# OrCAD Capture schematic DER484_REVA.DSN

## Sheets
1 PAGE3: size C
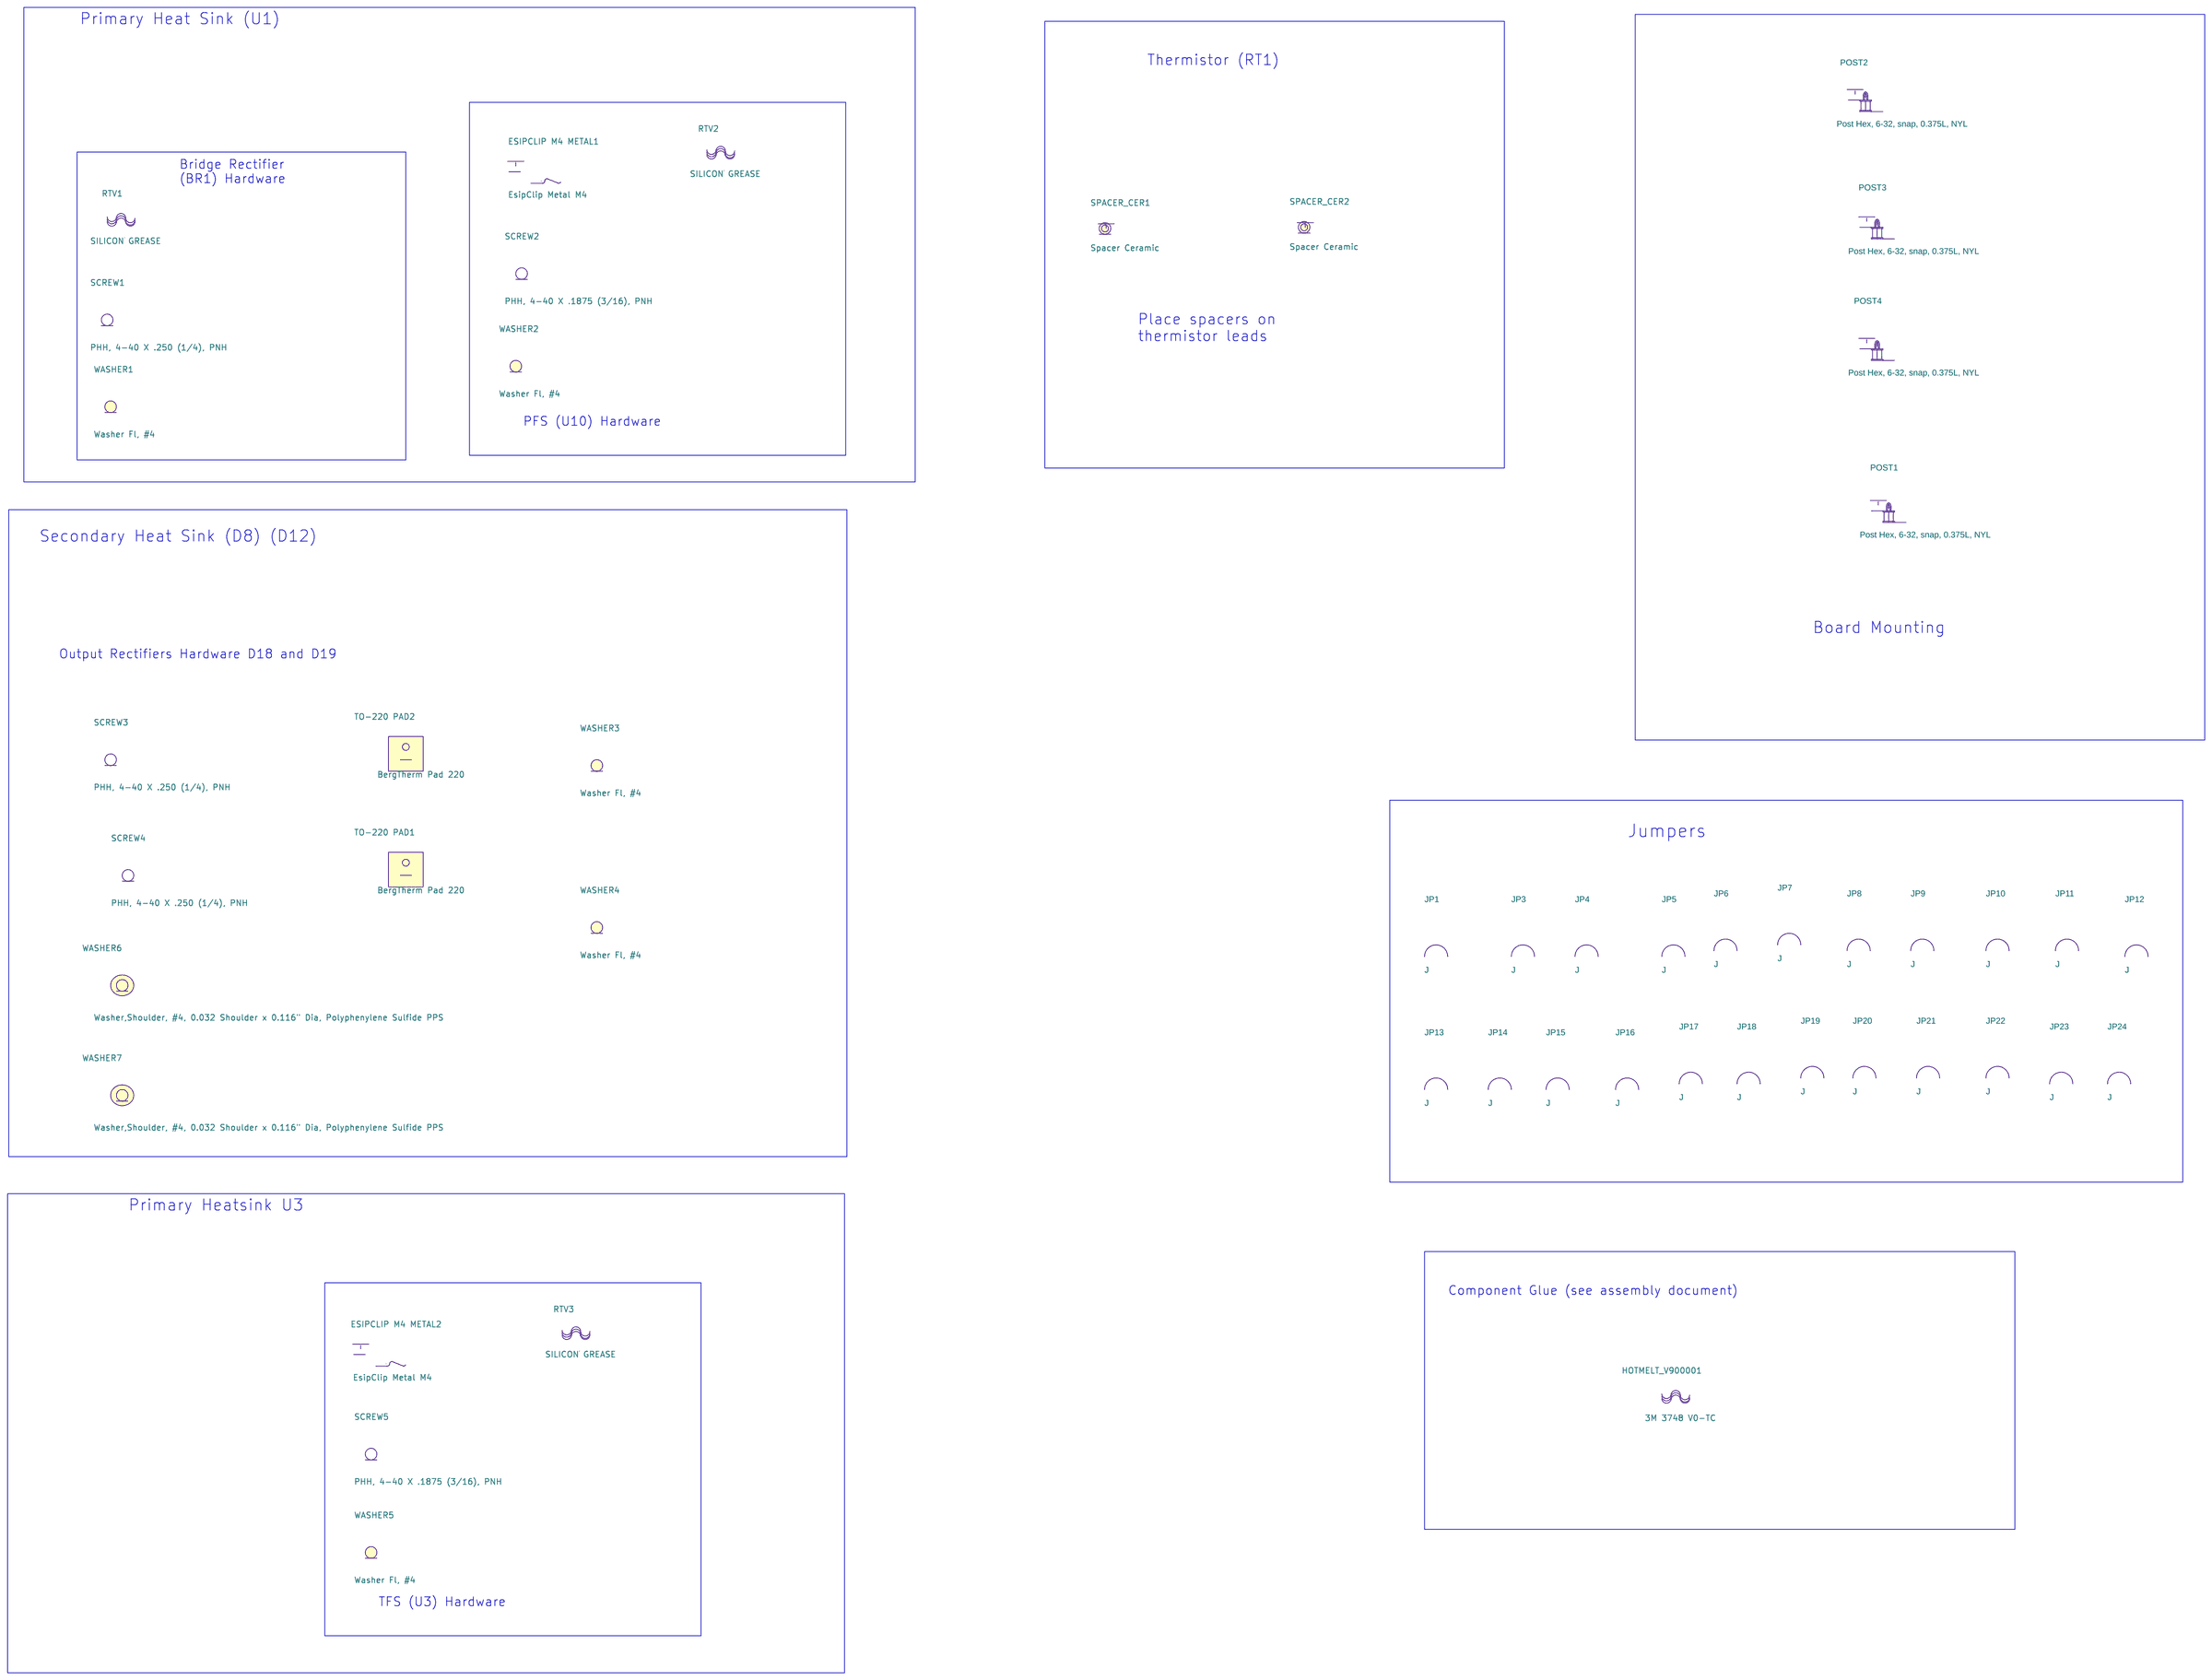
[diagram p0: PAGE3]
2 PAGE2: size C
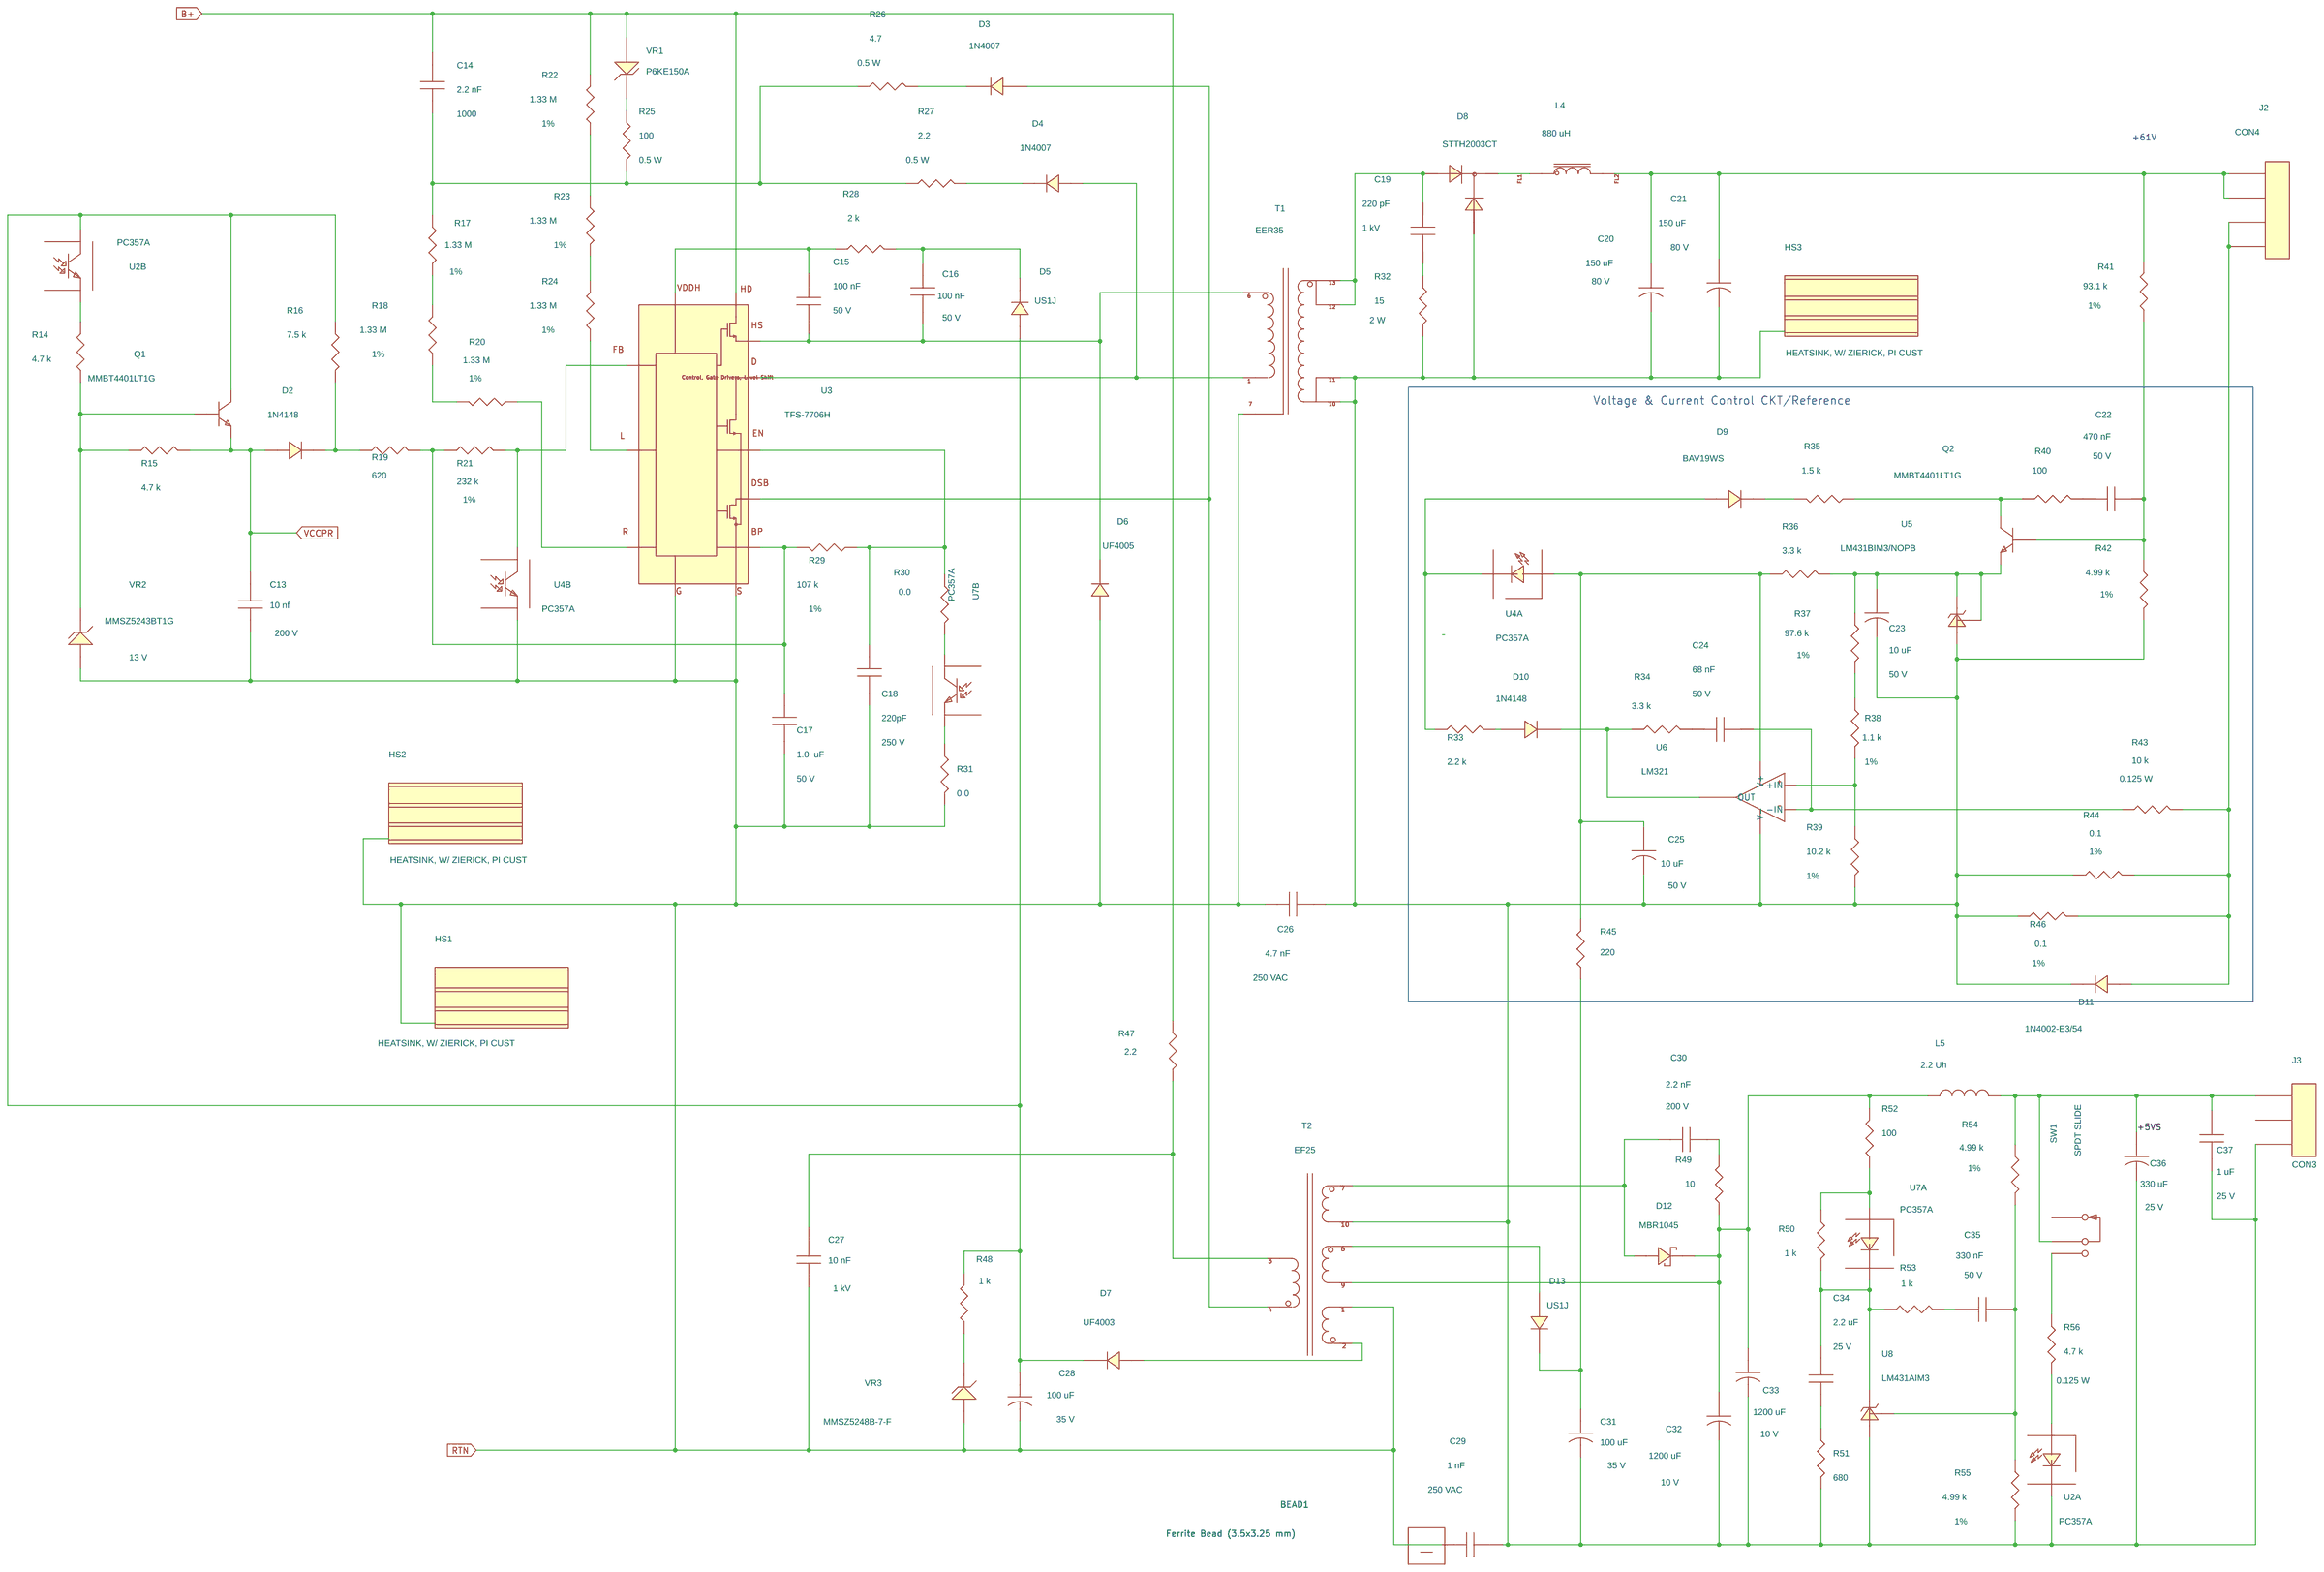
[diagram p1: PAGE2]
3 PAGE1: size C; title: DER-309; rev: A
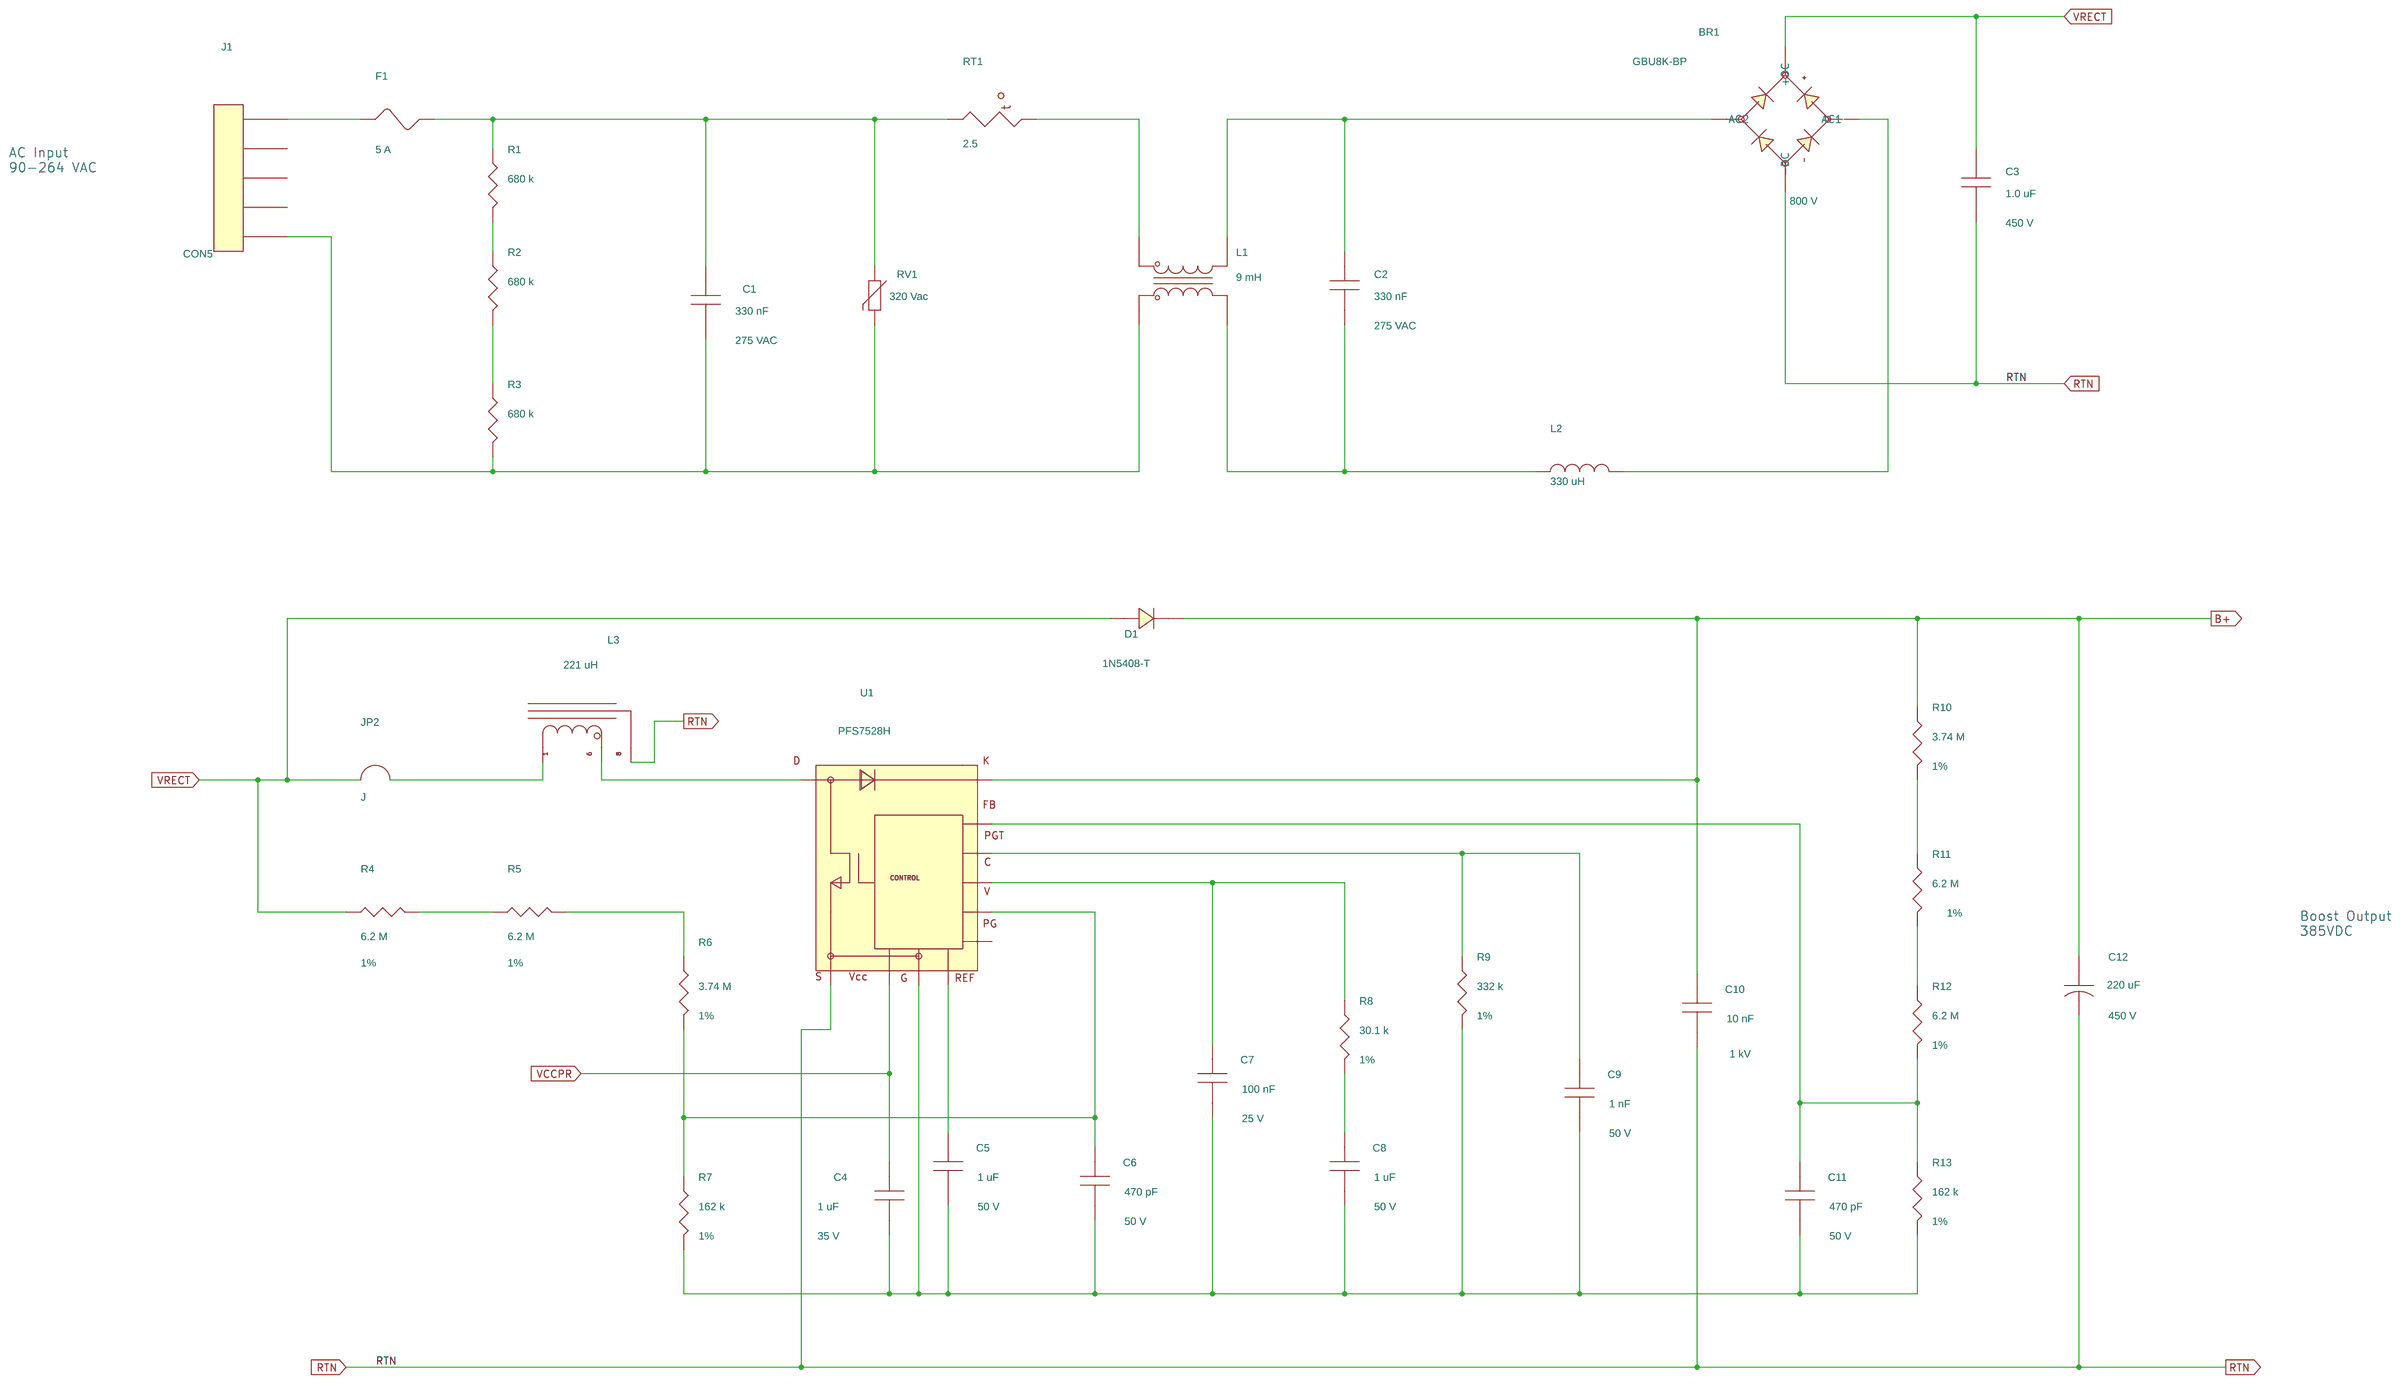
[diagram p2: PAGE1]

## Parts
sheet PAGE1
BR1  GBU8K-BP  [pidaxbridgegbu8]
C1  330 nF  [pinpcaprad760x380590050]
C2  330 nF  [pinpcaprad760x380590050]
C3  1.0 uF  [pi_np_cap_rad715x370ls590d050]
C4  1 uF  [pismc0603]
C5  1 uF  [pismc0805]
C6  470 pF  [pismc0805]
C7  100 nF  [pismc0805]
C8  1 uF  [pismc0805]
C9  1 nF  [pismc0805]
C10  10 nF  [pinpcaprad500x180250040]
C11  470 pF  [pismc0805]
C12  220 uF  [pi_polcap_cly_1181ls400d081]
D1  1N5408-T  [pidv300x200x060do15d0201ad]
F1  5 A  [pi_tr5_submin_fuse]
J1  CON5  [pi_hdr_5pin]
JP2  J  [pi_jumper200]
L1  9 mH  [pi_ind_4p_500x1050ls450d46_r1]
L2  330 uH  [pi_toroid_2p_550x950_ls480_d050]
L3  221 uH  [pi_bobbin_bpq32_20_DER484]
R1  680 k  [pismr1206]
R2  680 k  [pismr1206]
R3  680 k  [pismr1206]
R4  6.2 M  [pismr1206]
R5  6.2 M  [pismr1206]
R6  3.74 M  [pi14wvresd100ls100d030]
R7  162 k  [pismr0805]
R8  30.1 k  [pismr0805]
R9  332 k  [pismr0805]
R10  3.74 M  [pi14wvresd100ls100d030]
R11  6.2 M  [pismr1206]
R12  6.2 M  [pismr1206]
R13  162 k  [pismr0805]
RT1  2.5  [pi_rad180x395ls235d031]
RV1  320 Vac  [pidisc500x225ls335x140040]
U1  PFS7528H  [pi_ic_eesip_socket]
sheet PAGE2
BEAD1  Ferrite Bead (3.5x3.25 mm)
C13  10 nf  [pismc0805]
C14  2.2 nF  [pinpcaprad200x100200030]
C15  100 nF  [pismc0805]
C16  100 nF  [pismc0805]
C17  1.0  uF  [pinpcaprad200x100200030]
C18  220pF  [pismc0603]
C19  220 pF  [pinpcaprad250x100200030]
C20  150 uF  [pipolcapcyld400ls200040]
C21  150 uF  [pipolcapcyld400ls200040]
C22  470 nF  [pismc0805]
C23  10 uF  [pipolcapclyd200ls80030]
C24  68 nF  [pismc0805]
C25  10 uF  [pipolcapclyd200ls80030]
C26  4.7 nF  [pinpcaprad640x260375040]
C27  10 nF  [pinpcaprad500x180250040]
C28  100 uF  [pipolcapcyld250ls100030]
C29  1 nF  [pinpycaprad540x290ls400040]
C30  2.2 nF  [pismc0805]
C31  100 uF  [pipolcapcyld250ls100030]
C32  1200 uF  [pipolcapcyld400ls200040]
C33  1200 uF  [pipolcapcyld400ls200040]
C34  2.2 uF  [pismc0805]
C35  330 nF  [pismc0805]
C36  330 uF  [pipolcapcyld400ls200040]
C37  1 uF  [pismc1206]
D2  1N4148  [pidax375x070030do35]
D3  1N4007  [pidv200x110x040do41]
D4  1N4007  [pidax475x125040do41]
D5  US1J  [pismdsma]
D6  UF4005  [pidax475x125040do41]
D7  UF4003  [pidv200x110x040do41]
D8  STTH2003CT  [pidvto2203]
D9  BAV19WS  [pismsod323]
D10  1N4148  [pidax375x070030do35]
D11  1N4002-E3/54  [pidv200x110x040do41]
D12  MBR1045  [pidvt0220acreva]
D13  US1J  [pismdsma]
HS1  HEATSINK, W/ ZIERICK, PI CUST  [pi_hs_der484_bridge]
HS2  HEATSINK, W/ ZIERICK, PI CUST  [pi_hs_der484_esip]
HS3  HEATSINK, W/ ZIERICK, PI CUST  [pi_hs_der484_diodes]
J2  CON4  [PI_HDR_4PIN]
J3  CON3  [pi_hdr_3pin]
L4  880 uH  [pi_ind_2p_toroidal]
L5  2.2 Uh  [pi_choke_coilcraft_rfb0807]
Q1  MMBT4401LT1G  [pismsot23123_1]
Q2  MMBT4401LT1G  [pismsot23123_1]
R14  4.7 k  [pismr0805]
R15  4.7 k  [pismr0805]
R16  7.5 k  [pismr0603]
R17  1.33 M  [pismr1206]
R18  1.33 M  [pismr1206]
R19  620  [pismr0805]
R20  1.33 M  [pismr1206]
R21  232 k  [pismr0603]
R22  1.33 M  [pismr1206]
R23  1.33 M  [pismr1206]
R24  1.33 M  [pismr1206]
R25  100  [pi12wvresd180ls150d040]
R26  4.7  [pi12wvresd180ls150d040]
R27  2.2  [pi12wvresd180ls150d040]
R28  2 k  [pismr0805]
R29  107 k  [pi14wvresd100ls200d030]
R30  0.0  [pismr0805]
R31  0.0  [pismr0805]
R32  15  [pi2wvresd200ls300d040]
R33  2.2 k  [pismr0805]
R34  3.3 k  [pismr0805]
R35  1.5 k  [pismr1206]
R36  3.3 k  [pismr0805]
R37  97.6 k  [pismr0805]
R38  1.1 k  [pi14wresd100ls400d030]
R39  10.2 k  [pismr0805]
R40  100  [pismr0805]
R41  93.1 k  [pi14wresd100ls400d030]
R42  4.99 k  [pismr0805]
R43  10 k  [pi18wresd080ls300d030]
R44  0.1  [pismr2512]
R45  220  [pismr1206]
R46  0.1  [pismr2512]
R47  2.2  [pi12wvresd180ls150d040]
R48  1 k  [pismr0805]
R49  10  [pismr1206]
R50  1 k  [pismr0805]
R51  680  [pismr0805]
R52  100  [pismr0805]
R53  1 k  [pismr0805]
R54  4.99 k  [pismr0805]
R55  4.99 k  [pismr0805]
R56  4.7 k  [pi18wvresd80ls100d030]
SW1  SPDT SLIDE  [pi_switch_spdt_slide_pcbm_1]
T1  EER35  [pi_bobbin_eer35_14p_der484]
T2  EF25  [pi_bobbin_ef25_10p_der484]
U2  PC357A  [pi_4_smd]  (sections A,B)
U3  TFS-7706H  [pi_ic_esip16-12_oval_slot_recpt]
U4  PC357A  [pi_4_smd]  (sections A,B)
U5  LM431BIM3/NOPB  [pismsot23123]
U6  LM321  [pismsot235]
U7  PC357A  [pi_4_smd]  (sections A,B)
U8  LM431AIM3  [pismsot23123]
VR1  P6KE150A  [pidv200x140x050do15do204ac]
VR2  MMSZ5243BT1G  [pi_sm_sod-123_12]
VR3  MMSZ5248B-7-F  [pi_sm_sod-123_12]
sheet PAGE3
ESIPCLIP M4 METAL1  EsipClip Metal M4
ESIPCLIP M4 METAL2  EsipClip Metal M4
HOTMELT_V?#1  3M 3748 V0-TC
JP1  J  [pi_jumper900-18awg-sld]
JP3  J  [pi_jumper800-18awg-sld]
JP4  J  [pi_jumper600]
JP5  J  [pi_jumper1000]
JP6  J  [pi_jumper300]
JP7  J  [pi_jumper800]
JP8  J  [pi_jumper600-18awg-sld]
JP9  J  [pi_jumper700]
JP10  J  [pi_jumper500]
JP11  J  [pi_jumper400]
JP12  J  [pi_jumper300-18awg-sld]
JP13  J  [pi_jumper400-18awg-sld]
JP14  J  [pi_jumper900-18awg-sld]
JP15  J  [pi_jumper600-18awg-sld]
JP16  J  [pi_jumper2300-18awg-sld]
JP17  J  [pi_jumper800]
JP18  J  [pi_jumper500]
JP19  J  [pi_jumper800-18awg-sld]
JP20  J  [pi_jumper300]
JP21  J  [pi_jumper1000]
JP22  J  [pi_jumper300]
JP23  J  [pi_jumper300]
JP24  J  [pi_jumper800-18awg-sld]
POST1  Post Hex, 6-32, snap, 0.375L, NYL  [pimtgholed156]
POST2  Post Hex, 6-32, snap, 0.375L, NYL  [pimtgholed156]
POST3  Post Hex, 6-32, snap, 0.375L, NYL  [pimtgholed156]
POST4  Post Hex, 6-32, snap, 0.375L, NYL  [pimtgholed156]
RTV1  SILICON GREASE
RTV2  SILICON GREASE
RTV3  SILICON GREASE
SCREW1  PHH, 4-40 X .250 (1/4), PNH
SCREW2  PHH, 4-40 X .1875 (3/16), PNH
SCREW3  PHH, 4-40 X .250 (1/4), PNH
SCREW4  PHH, 4-40 X .250 (1/4), PNH
SCREW5  PHH, 4-40 X .1875 (3/16), PNH
SPACER_CER1  Spacer Ceramic
SPACER_CER2  Spacer Ceramic
TO-220 PAD1  BergTherm Pad 220
TO-220 PAD2  BergTherm Pad 220
WASHER1  Washer Fl, #4
WASHER2  Washer Fl, #4
WASHER3  Washer Fl, #4
WASHER4  Washer Fl, #4
WASHER5  Washer Fl, #4
WASHER6  Washer,Shoulder, #4, 0.032 Shoulder x 0.116" Dia, Polyphenylene Sulfide PPS
WASHER7  Washer,Shoulder, #4, 0.032 Shoulder x 0.116" Dia, Polyphenylene Sulfide PPS

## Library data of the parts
BR1 = DISCRETE_BRIDGE_+~~-: ALT_SYMBOLS: pidaxbridgegbu8_horz; Disp_Voltage: 800 V; Part Number: 15-00347-00
C1 C2 = CAP_NP: Disp_Voltage: 275 VAC; Part Number: 20-00542-00; Voltage: 275 VAC
C3 = CAP_NP: Disp_Voltage: 450 V; Part Number: 20-00971-00; Voltage: 450 V
C4 = CAP_NP: Disp_Voltage: 35 V; Part Number: 20-01134-00; Voltage: 35 V
C5 C8 = CAP_NP: Disp_Voltage: 50 V; Part Number: 20-01022-00; Voltage: 50 V
C6 C11 = CAP_NP: Disp_Voltage: 50 V; Part Number: 20-00205-00; Voltage: 50 V
C7 = CAP_NP: Disp_Voltage: 25 V; Part Number: 20-08599-00; Voltage: 25 V
C9 = CAP_NP: Disp_Voltage: 50 V; Part Number: 20-08750-00; Voltage: 50 V
C10 C27 = CAP_NP: Disp_Voltage: 1 kV; Part Number: 20-00634-00; Voltage: 1 kV
C12 = CAP_POL: Disp_Voltage: 450 V; Part Number: 20-08731-00; Voltage: 450 V
D1 = DIODE: ALT_SYMBOLS: pidax800x225060do15do201ad,pidv300x200x060do14wbead; FPLIST: pidv300x200x060do15d0201ad,pidax800x225060do15do201ad,pidv300x200x060do14wbead; Part Number: 15-00719-00
F1 = FUSE: Part Number: 40-00005-00
J1 = CON5: Part Number: 35-00242-00
JP2 = JUMPER_1: Part Number: 65-00001-00
L1 = INDUCTOR_4P_revB: FPLIST: pi_ind_4p_500x1050ls450d46,pi_ind_4p_500x1050ls450d46_r1; Part Number: 30-00235-00
L2 = INDUCTOR: Part Number: 32-00295-00
L3 = INDUCTOR_DER484_PFC: Part Number: 32-00324-00
R1-R3 = R: Part Number: 05-01420-00
R4 R5 R11 R12 = R: Disp_Tol: 1%; Part Number: 05-05567-00
R6 R10 = R: ALT_SYMBOLS: pi14wvresd100ls200d030,pi14wresd100ls400d030,pi14wresd100ls500d030; Disp_Tol: 1%; FPLIST: pi14wvresd100ls100d030,pi14wvresd100ls200d030,pi14wresd100ls400d030,pi14wresd100ls500d030; Part Number: 05-05566-00
R7 R13 = R: Disp_Tol: 1%; Part Number: 05-00800-00
R8 = R: Disp_Tol: 1%; Part Number: 05-00730-00
R9 = R: Disp_Tol: 1%; Part Number: 05-00830-00
RT1 = THERMISTOR: ALT_SYMBOLS: pirad550x410ls300040_h; FPLIST: pi_rad180x395ls235d031,pirad550x410ls300040_h; Part Number: 90-00038-00
RV1 = VARISTOR: ALT_SYMBOLS: pi_rad450x550ls300d040_h; Part Number: 85-00018-00
U1 = DEV_HIPERPFS-3-eSIP-16C: ALT_SYMBOLS: pi_ic_esip16-13_socket_hpii ,pi_ic_esip16-13_oval_hpii,pi_ic_eesip_socket; FPLIST: pi_ic_esip16-13_slot_hpii,pi_ic_esip16-13_socket_hpii,pi_ic_esip16-13_oval_hpii,pi_ic_eesip_socket; Part Number: 10-00691-00
BEAD1 = Bead: Part Number: 30-00117-00
C13 = CAP_NP: Disp_Voltage: 200 V; Part Number: 20-00531-00; Voltage: 200 V
C14 = CAP_NP: Disp_Voltage: 1000; Part Number: 20-01093-00; Voltage: 1000
C15 C16 = CAP_NP: Disp_Voltage: 50 V; Part Number: 20-00904-00; Voltage: 50 V
C17 = CAP_NP: Disp_Voltage: 50 V; Part Number: 20-01142-00; Voltage: 50 V
C18 = CAP_NP: Disp_Voltage: 250 V; Part Number: 20-00840-00; Voltage: 250 V
C19 = CAP_NP: Disp_Voltage: 1 kV; Part Number: 20-00354-00; Voltage: 1 kV
C20 C21 = CAP_POL: Disp_Voltage: 80 V; Part Number: 20-08911-00; Voltage: 80 V
C22 = CAP_NP: Disp_Voltage: 50 V; Part Number: 20-00896-00; Voltage: 50 V
C23 C25 = CAP_POL: ALT_SYMBOLS: pipolcapclyd200ls80030h; Disp_Voltage: 50 V; FPLIST: pipolcapclyd200ls80030,pipolcapclyd200ls80030h; Part Number: 20-00443-00; Voltage: 50 V
C24 = CAP_NP: Disp_Voltage: 50 V; Part Number: 20-00231-00; Voltage: 50 V
C26 = CAP_NP: Disp_Voltage: 250 VAC; Part Number: 20-00378-00; Voltage: 250 VAC
C28 = CAP_POL: ALT_SYMBOLS: pipolcapclyd250ls100d30h590; COMPGROUP: 1; Disp_Voltage: 35 V; FPLIST: pipolcapcyld250ls100030,pipolcapclyd250ls100d30h590; Part Number: 20-00117-00; Tol: 20; Voltage: 35 V
C29 = CAP_NP: ALT_SYMBOLS: pinpycaprad540x290ls400040h; Disp_Voltage: 250 VAC; FPLIST: pinpycaprad540x290ls400040,pinpycaprad540x290ls400040h; Part Number: 20-00375-00; Voltage: 250 VAC
C30 = CAP_NP: Disp_Voltage: 200 V; Part Number: 20-00761-00; Voltage: 200 V
C31 = CAP_POL: ALT_SYMBOLS: pipolcapclyd250ls100d30h590; Disp_Voltage: 35 V; FPLIST: pipolcapcyld250ls100030,pipolcapclyd250ls100d30h590; Part Number: 20-00117-00; Voltage: 35 V
C32 C33 = CAP_POL: Disp_Voltage: 10 V; Part Number: 23-00060-00; Voltage: 10V
C34 = CAP_NP: Disp_Voltage: 25 V; Part Number: 20-08603-00; Voltage: 25 V
C35 = CAP_NP: Disp_Voltage: 50 V; Part Number: 20-00895-00; Voltage: 50 V
C36 = CAP_POL: ALT_SYMBOLS: pipolcapclyd400x530ls200030h; Disp_Voltage: 25 V; Part Number: 20-00100-00; Voltage: 25 V
C37 = CAP_NP: Disp_Voltage: 25 V; Part Number: 20-00897-00; Voltage: 25 V
D2 D10 = DIODE: ALT_SYMBOLS: pidax375x070030do35,pidv100x080x030do35; FPLIST: pidv200x080x030do35,pidax375x070030do35,pidv100x080x030do35; Part Number: 15-00083-00
D3 D4 = DIODE: ALT_SYMBOLS: pidax475x125040do41,pidv200x110x040do41wbead,pidax390x125040do41; FPLIST: pidv200x110x040do41,pidax475x125040do41,pidv200x110x040do41wbead,pidax390x125040do41; Part Number: 15-00623-00
D5 = DIODE: Part Number: 15-00494-00
D6 = DIODE: ALT_SYMBOLS: pidax475x125040do41,pidax390x125040do41; FPLIST: pidv200x110x040do41,pidax475x125040do41,pidax390x125040do41; Part Number: 15-00109-00
D7 = DIODE: ALT_SYMBOLS: pidax475x125040do41,pidv200x110x040do41wbead,pidax390x125040do41; COMPGROUP: 1; FPLIST: PI_DV/.200X.110X.040/DO_41,PI_DAX/.475X.125/.040/DO_41,PI_DV/.200X.110X.040/DO_41_WBEAD,PI_DAX/.390X.125/.040/DO_41; Part Number: 15-00107-00
D8 = D_DUAL_CK_ACA_4: ALT_SYMBOLS: pidvto2203vf1; FPLIST: pidvto2203,pidvto2203vf1; Part Number: 15-01131-00
D9 = DIODE: Part Number: 15-00658-00
D11 = DIODE: ALT_SYMBOLS: pidax475x125040do41,pidv200x110x040do41wbead,pidax390x125040do41; FPLIST: pidv200x110x040do41,pidax475x125040do41,pidv200x110x040do41wbead,pidax390x125040do41; Part Number: 15-00792-00
D12 = DIODE_SCHOTTKY: Part Number: 15-00147-00
D13 = DIODE: COMPGROUP: 1; Part Number: 15-00494-00
HS1 = HS-PI_CUSTOM2: Part Number: 61-00196-01
HS2 = HS-PI_CUSTOM2: Part Number: 61-00197-01
HS3 = HS-PI_CUSTOM2: Part Number: 61-00198-01
J2 = CON4: COMPGROUP: 2; Part Number: 35-00003-00
J3 = CON3: Part Number: 35-00002-00
L4 = INDUCTOR_DER484: Part Number: 32-00322-00
L5 = INDUCTOR: Part Number: 30-00161-00
Q1 Q2 = NPN_BEC: Part Number: 55-00059-00
R14 R15 = R: Part Number: 05-01535-00
R16 = R: Part Number: 05-01709-00
R17 R18 R20 R22 = R: Disp_Tol: 1%; Part Number: 05-05444-00
R19 = R: Part Number: 05-01514-00
R21 = R: Disp_Tol: 1%; Part Number: 05-01209-00
R23 R24 = R: COMPGROUP: 2; Disp_Tol: 1%; Part Number: 05-05444-00; Tol: 1%
R25 = R: ALT_SYMBOLS: pi12wvresd180ls200d040,pi12wvresd180ls250d040,pi12wresd180ls675d040; Disp_Power: 0.5 W; FPLIST: pi12wvresd180ls150d040,pi12wvresd180ls200d040,pi12wvresd180ls250d040,pi12wresd180ls675d040; Part Number: 05-05569-00
R26 = R: ALT_SYMBOLS: pi12wvresd180ls200d040,pi12wvresd180ls250d040,pi12wresd180ls675d040; Disp_Power: 0.5 W; FPLIST: pi12wvresd180ls150d040,pi12wvresd180ls200d040,pi12wvresd180ls250d040,pi12wresd180ls675d040; Part Number: 05-02619-00
R27 = R: ALT_SYMBOLS: pi12wvresd180ls200d040,pi12wvresd180ls250d040,pi12wresd180ls675d040; Disp_Power: 0.5 W; FPLIST: pi12wvresd180ls150d040,pi12wvresd180ls200d040,pi12wvresd180ls250d040,pi12wresd180ls675d040; Part Number: 05-02611-00
R28 = R: Part Number: 05-01526-00
R29 = R: ALT_SYMBOLS: pi14wvresd100ls200d030,pi14wresd100ls400d030,pi14wresd100ls500d030; Disp_Tol: 1%; FPLIST: pi14wvresd100ls100d030,pi14wvresd100ls200d030,pi14wresd100ls400d030,pi14wresd100ls500d030; Part Number: 05-02171-00
R30 R31 = R: Part Number: 05-03159-00
R32 = R: ALT_SYMBOLS: pi2wresd200ls900d040,pi2wvresd200ls300d040,pi2wvresd200ls400d040; Disp_Power: 2 W; FPLIST: pi2wresd200ls725d040,pi2wresd200ls900d040,pi2wvresd200ls300d040,pi2wvresd200ls400d040; Part Number: 05-02960-00
R33 = R: Part Number: 05-01527-00
R34 R36 = R: Part Number: 05-01531-00
R35 = R: Part Number: 05-01356-00
R37 = R: Disp_Tol: 1%; Part Number: 05-00779-00
R38 = R: ALT_SYMBOLS: pi14wvresd100ls200d030,pi14wresd100ls400d030,pi14wresd100ls500d030; Disp_Tol: 1%; FPLIST: pi14wvresd100ls100d030,pi14wvresd100ls200d030,pi14wresd100ls400d030,pi14wresd100ls500d030; Part Number: 05-01980-00
R39 = R: Disp_Tol: 1%; Part Number: 05-00685-00
R40 R52 = R: Part Number: 05-01495-00
R41 = R: ALT_SYMBOLS: pi14wvresd100ls200d030,pi14wresd100ls400d030,pi14wresd100ls500d030; Disp_Tol: 1%; FPLIST: pi14wvresd100ls100d030,pi14wvresd100ls200d030,pi14wresd100ls400d030,pi14wresd100ls500d030; Part Number: 05-02165-00
R42 R54 R55 = R: Disp_Tol: 1%; Part Number: 05-03373-00
R43 = R: COMPGROUP: 5; Disp_Power: 0.125 W; FPLIST: pi18wvresd80ls100d030,pi18wresd080ls300d030; PCB Editor PCBFP: pismr0805; Part Number: 05-02361-00; Tol: 1%
R44 R46 = R: Disp_Tol: 1%; Part Number: 05-06320-00
R45 = R: Part Number: 05-01336-00
R47 = R: ALT_SYMBOLS: pi12wvresd180ls200d040,pi12wvresd180ls250d040,pi12wresd180ls675d040; FPLIST: pi12wvresd180ls150d040,pi12wvresd180ls200d040,pi12wvresd180ls250d040,pi12wresd180ls675d040; Part Number: 05-05578-00
R48 R50 R53 = R: Part Number: 05-01519-00
R49 = R: Part Number: 05-01304-00
R51 = R: Part Number: 05-01515-00
R56 = R: ALT_SYMBOLS: pi18wresd080ls300d030; Disp_Power: 0.125 W; FPLIST: pi18wvresd80ls100d030,pi18wresd080ls300d030; Part Number: 05-02353-00
SW1 = SW_SLIDE-SPDT: Part Number: 66-00111-00
T1 = BEER35_CUSTOM_DER484: Part Number: 25-01070-00
T2 = BEF25_CUSTOM_DER484: Part Number: 25-01069-00
U2 U4 U7 = OPTO_A_B: Part Number: 53-00003-00
U3 = HiperTFS_II_I_2_ROW: FPLIST: pi_ic_esip16-12_oval_slot,pi_ic_esip16-12_oval_slot_recpt; Part Number: 10-00611-00
U5 = TL431_SOT-23_CAR: Part Number: 45-00232-00
U6 = LM321_SOT23-5: Part Number: 45-00049-00
U8 = TL431_SOT-23_CAR: Part Number: 45-00268-00
VR1 = DIODE_ZENER: ALT_SYMBOLS: pidax550x140050do15do204ac; FPLIST: pidv200x140x050do15do204ac,pidax550x140050do15do204ac; Part Number: 15-00619-00
VR2 = DIODE_ZENER: Disp_Voltage: 13 V; Part Number: 15-00710-00
VR3 = DIODE_ZENER: Part Number: 15-01105-00
ESIPCLIP M4 METAL1 ESIPCLIP M4 METAL2 = EsipClip_Metal_M4: Part Number: 60-00042-00
HOTMELT_V?#1 = HOTMELT-V0: Part Number: 66-00077-00
JP1 JP14 = JUMPER_1: Part Number: 65-00087-00
JP3 JP19 JP24 = JUMPER_1: Part Number: 65-00086-00
JP4 = JUMPER_1: Part Number: 65-00123-00
JP5 = JUMPER_1: Part Number: 65-00009-00
JP6 JP22 = JUMPER_1: Part Number: 65-00120-00
JP7 JP17 = JUMPER_1: Part Number: 65-00125-00
JP8 JP15 = JUMPER_1: Part Number: 65-00084-00
JP9 = JUMPER_1: Part Number: 65-00124-00
JP10 = JUMPER_1: Part Number: 65-00004-00
JP11 = JUMPER_1: Part Number: 65-00003-00
JP12 = JUMPER_1: Part Number: 65-00081-00
JP13 = JUMPER_1: Part Number: 65-00082-00
JP16 = JUMPER_1: Part Number: 65-00181-00
JP18 = JUMPER_1: Part Number: 65-00122-00
JP20 JP23 = JUMPER_1: Part Number: 65-00002-00
JP21 = JUMPER_1: Part Number: 65-00127-00
POST1-POST4 = POST_CRKT_BRD_6-32_HEX: Part Number: 76-00003-00
RTV1-RTV3 = RTV: Part Number: 66-00084-00
SCREW1 SCREW3 SCREW4 = SCR_4-40: Part Number: 75-00001-00
SCREW2 SCREW5 = SCR_4-40: Part Number: 75-00089-00
SPACER_CER1 SPACER_CER2 = Spacer_Ceramic: Part Number: 76-00031-00
TO-220 PAD1 TO-220 PAD2 = Berguist_TO-220_Pad: Part Number: 66-00079-00
WASHER1 = WASH_FLAT_4: Part Number: 75-00032-00
WASHER2-WASHER5 = WASH_FLAT_4: Part Number: 75-00164-00
WASHER6 WASHER7 = WASH_SHLDR_4: Part Number: 75-00152-00

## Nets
+5VS: C36.1 C37.1 J3.1 L5.2 R54.1 SW1.2
VCCPR: C4.1 C13.2 D2.2 Q1.2(EMITTER) R15.1 U1.1(Vcc)
B+: C10.1 C12.1 C14.2 D1.1 R10.1 R22.2 R47.1 U1.16(K) U3.16(HD) VR1.2
NC: U1.14(NC)
RTN: BR1.4(-DC) C3.2 C10.2 C12.2 C13.1 C17.2 C18.2 C26.1 C27.1 C28.2 C29.1 D6.2 HS1.1 HS2.1 L3.8 R31.2 T1.7 T2.1 U1.10(S1) U3.5(G) U3.6(S) U4.3(E) VR2.2 VR3.2
SOURCE: U1.11(SOURCE)
VRECT: BR1.1(+DC) C3.1 D1.2 JP2.1 R4.1
N8573798: C20.2 C21.2 C23.2 C25.2 C26.2 C29.2 C31.2 C32.2 C33.2 C36.2 C37.2 D8.1(A1) D11.1 HS3.1 J3.3 R32.2 R39.2 R42.2 R44.1 R46.1 R51.2 R55.2 T1.10 T1.11 T2.10 U2.2(C) U5.2(A) U6.2(V-) U8.2(A)
N8573822: D8.2(CATHODE) L4.1
N8573908: C15.2 C16.2 D6.1 T1.6 U3.14(HS)
N8573924: C14.1 R17.1 R25.2 R26.1 R27.1
N8573984: C23.1 Q2.2(EMITTER) R36.2 R37.1 U5.1(C) U5.3(VREF)
N8573988: C15.1 R28.1 U3.13(VDDH)
N8574066: R23.2 R24.2
N8574082: D4.2 T1.1 U3.1(D)
N8574090: C17.1 R19.1 R21.1 R29.1 U3.11(BP)
N8574122: D11.2 J2.3 J2.4 R43.2 R44.2 R46.2
N8574162: C18.1 R29.2 R30.1 U3.8(EN)
N8574170: C19.1 D8.3(A2) T1.12 T1.13
N8574254: R20.1 U3.7(R)
N8574324: R24.1 U3.9(L)
N8574348: C20.1 C21.1 J2.1 J2.2 L4.2 R41.2
N8574438: R21.2 U3.10(FB) U4.4(C)
N8574464: C25.1 R36.1 R45.2 U4.1(A) U6.5(V+)
N8574666: C32.1 C33.1 D12.1 L5.1 R49.1 R52.2 T2.9
N8574858: C28.1 D5.2 D7.1 Q1.3(COLLECTOR) R16.2 R48.2 U2.4(C)
N8574878: C27.2 R47.2 T2.3
N8574990: D3.2 T2.4 U3.3(DSB)
N8575976: C19.2 R32.1
N8576150: R38.2 R39.1 U6.1(+IN)
N8576178: D10.1 R34.1 U6.4(OUT)
N8576798: R18.2 R20.2
N8576938: R50.1 R52.1 U7.1(A)
N8576942: C34.2 R50.2 R53.1 U7.2(C) U8.1(C)
N8577402: C35.2 R54.2 R55.1 U8.3(VREF)
N8577904: R17.2 R18.1
N8578122: R22.1 R23.1
N8582199: Q1.1(BASE) R14.1 R15.2 VR2.1
N8582213: D2.1 R16.1 R19.2
N8613531: C24.2 R43.1 U6.3(-IN)
N8617835: C34.1 R51.1
N8621032: C4.2 C5.2 C6.2 C7.2 C8.2 C9.2 C11.2 R7.2 R9.2 R13.2 U1.4(G)
N8621040: C9.1 R9.1 U1.9(PGT)
N8621064: C8.1 R8.2
N8621068: C7.1 R8.1 U1.6(C)
N8621110: C6.1 R6.2 R7.1 U1.5(V)
N8621154: C5.1 U1.3(REF)
N8621242: JP2.2 L3.1
N8621246: C1.2 J1.5 L1.1 R3.2 RV1.2
N8621358: C2.2 L1.2 L2.1
N8621428: BR1.2(AC1) L2.2
N8621454: R1.2 R2.1
N8621482: C1.1 F1.2 R1.1 RT1.1 RV1.1
N8621528: F1.1 J1.1
N8621724: BR1.3(AC2) C2.1 L1.4
N8621808: R4.2 R5.1
N8621812: R5.2 R6.1
N8622000: L1.3 RT1.2
N8622846: C11.1 R12.2 R13.1 U1.7(FB)
N8622966: R10.2 R11.1
N8622970: R11.2 R12.1
N8625218: R2.2 R3.1
N8628411: R25.1 VR1.1
N8629085: R30.2 U7.4(C)
N8629124: D4.1 R27.2
N8637240: C35.1 R53.2
N8639668: D3.1 R26.2
N8650505: R14.2 U2.3(E)
N8659234: R56.1 SW1.3
N8659238: R56.2 U2.1(A)
N8678796: C16.1 D5.1 R28.2
N8704340: C22.2 Q2.1(BASE) R41.1 R42.1
N8715929: Q2.3(COLLECTOR) R35.1 R40.1
N8730428: D9.2 R33.1 U4.2(C)
N8731215: D9.1 R35.2
N8736247: C31.1 D13.1 R45.1
N8746626: C30.1 D12.2 T2.7
N8749328: D10.2 R33.2
N8758678: R37.2 R38.1
N8762816: R31.1 U7.3(E)
N8800122: D13.2 T2.6
N8801044: C30.2 R49.2
N8805084: D7.2 T2.2
N8807537: R48.1 VR3.1
N8808690: L3.6 U1.13(D)
N8825099: C24.1 R34.2
N8825100: C22.1 R40.2

Not connected (* = marked no-connect by the designer): HS1 2; HS2 2; HS3 2; J1 2 3 4; J3 2; JP1 1 2; JP3 1 2; JP4 1 2; JP5 1 2; JP6 1 2; JP7 1 2; JP8 1 2; JP9 1 2; JP10 1 2; JP11 1 2; JP12 1 2; JP13 1 2; JP14 1 2; JP15 1 2; JP16 1 2; JP17 1 2; JP18 1 2; JP19 1 2; JP20 1 2; JP21 1 2; JP22 1 2; JP23 1 2; JP24 1 2; POST1 1; POST2 1; POST3 1; POST4 1; SW1 1; U1 8(PG)

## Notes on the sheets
sheet 1
- Primary Heat Sink (U1)
- Thermistor (RT1)
- Bridge Rectifier
  (BR1) Hardware
- Place spacers on
  thermistor leads
- PFS (U10) Hardware
- Secondary Heat Sink (D8) (D12)
- Board Mounting
- Output Rectifiers Hardware D18 and D19
- Jumpers
- Primary Heatsink U3
- Component Glue (see assembly document)
- TFS (U3) Hardware
sheet 2
- +61V
- Voltage & Current Control CKT/Reference
sheet 3
- AC Input
  90-264 VAC
- Boost Output
  385VDC
